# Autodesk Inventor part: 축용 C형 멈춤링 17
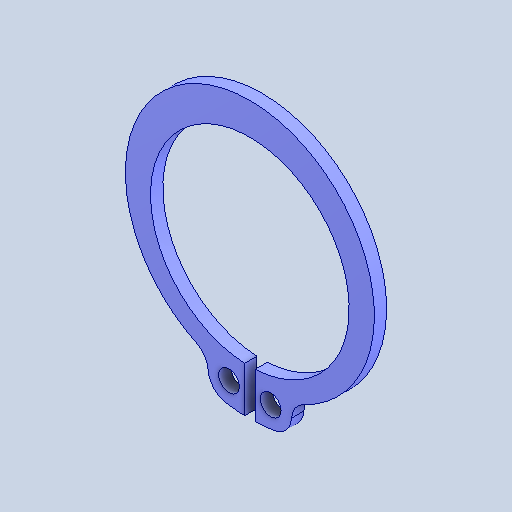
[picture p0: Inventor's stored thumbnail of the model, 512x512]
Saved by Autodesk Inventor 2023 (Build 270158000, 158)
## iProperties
Created: 2026-04
Part Number: 축용 C형 멈춤링 17
Material: 강철, 연강
Description: 리테이닝 링(C형)
Document SubType Name: Modeling
Designer: home
Density: 7.85 g/cm^3
Appearance: 기본값
Author: jhkim
Sending System: Autodesk Inventor 2027
Preprocessor: ST-DEVELOPER v20.1
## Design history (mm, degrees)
feature "Solid1"
node "솔리드1"
